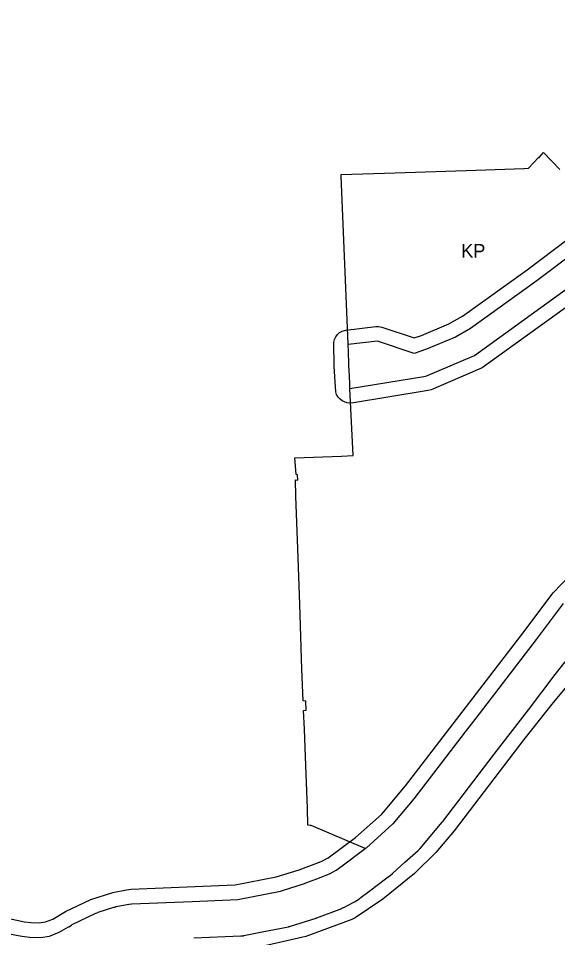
# Model space of a CAD drawing. Extents: x 7428080 to 7432143, y 5545880 to 5549217.
# Drawn here: x 7429439.3 to 7429660.4, y 5546644.6 to 5547021.6 of the extents above; entities that cross this region are included whole.
import ezdxf

# ---------------------------------------------------------------- set-up
doc = ezdxf.new("R2010")
doc.units = 0
for name, color, linetype in [('CZ_L_linie rozgraniczające tereny o różnym przeznaczeniu oraz różnych warunkach ich zabudowy i zagospodarowania', 7, 'Continuous'), ('CZ_L_maksymalne nieprzekraczalne linie zabudowy', 7, 'Continuous'), ('CZ_L_opisy_linie rozgraniczające tereny o różnym przeznaczeniu oraz różnych warunkach ich zabudowy i zagospodarowania', 7, 'Continuous')]:
    doc.layers.add(name, color=color, linetype=linetype)

msp = doc.modelspace()

# ---------------------------------------------------------------- linework, layer by layer
at = {"layer": 'CZ_L_linie rozgraniczające tereny o różnym przeznaczeniu oraz różnych warunkach ich zabudowy i zagospodarowania'}
for p, q in [((7429652.76, 5546964.51), (7429653.66, 5546965.56)), ((7429653.66, 5546965.56), (7429654.57, 5546966.64)), ((7429654.57, 5546966.64), (7429661.31, 5546959.61)), ((7429648.41, 5546960.26), (7429652.59, 5546964.55)), ((7429652.59, 5546964.55), (7429652.62, 5546964.67)), ((7429652.62, 5546964.67), (7429652.66, 5546964.62)), ((7429652.66, 5546964.62), (7429652.76, 5546964.51)), ((7429571.61, 5546957.53), (7429593.78, 5546958.24)), ((7429593.78, 5546958.24), (7429627.02, 5546959.43)), ((7429627.02, 5546959.43), (7429646.55, 5546960.01)), ((7429646.55, 5546960.01), (7429646.7, 5546960.03)), ((7429646.7, 5546960.03), (7429648.41, 5546960.26)), ((7429571.55, 5546956.84), (7429571.61, 5546957.53)), ((7429574.52, 5546888.1), (7429571.55, 5546956.84)), ((7429684.54, 5546938.62), (7429651.42, 5546913.65)), ((7429651.42, 5546913.65), (7429624.59, 5546894.44)), ((7429624.59, 5546894.44), (7429618.47, 5546890.9)), ((7429618.47, 5546890.9), (7429606.67, 5546885.9)), ((7429574.53, 5546887.87), (7429574.52, 5546888.1)), ((7429586.45, 5546889.23), (7429574.53, 5546887.87)), ((7429574.6, 5546884.87), (7429574.53, 5546887.87)), ((7429601.5, 5546884.24), (7429586.45, 5546889.23)), ((7429574.72, 5546879.87), (7429574.6, 5546884.87)), ((7429606.67, 5546885.9), (7429601.5, 5546884.24)), ((7429574.74, 5546879.06), (7429574.72, 5546879.87)), ((7429574.97, 5546874.96), (7429574.74, 5546879.06)), ((7429575.14, 5546871.42), (7429574.97, 5546874.96)), ((7429575.21, 5546869.82), (7429575.14, 5546871.42)), ((7429576.52, 5546842.27), (7429575.21, 5546869.82)), ((7429552.56, 5546841.32), (7429571.74, 5546842.1)), ((7429553.1, 5546834.5), (7429552.56, 5546841.32)), ((7429571.74, 5546842.1), (7429576.52, 5546842.27)), ((7429553.72, 5546834.43), (7429553.1, 5546834.5)), ((7429553.81, 5546832.24), (7429553.72, 5546834.43)), ((7429552.98, 5546825.67), (7429552.84, 5546832.29)), ((7429552.84, 5546832.29), (7429553.81, 5546832.24)), ((7429553.81, 5546804.08), (7429552.98, 5546825.67)), ((7429554.69, 5546781.35), (7429553.81, 5546804.08)), ((7429555.55, 5546754.68), (7429554.69, 5546781.35)), ((7429662.65, 5546781.62), (7429651.62, 5546766.91)), ((7429651.62, 5546766.91), (7429626.79, 5546734.57)), ((7429556.08, 5546741.71), (7429555.55, 5546754.68)), ((7429659.42, 5546752.44), (7429663.45, 5546757.68)), ((7429648.37, 5546738.05), (7429659.42, 5546752.44)), ((7429557.13, 5546741.58), (7429556.08, 5546741.71)), ((7429557.28, 5546737.9), (7429557.13, 5546741.58)), ((7429556.24, 5546737.69), (7429557.28, 5546737.9)), ((7429556.58, 5546730.1), (7429556.24, 5546737.69)), ((7429634.38, 5546719.82), (7429648.37, 5546738.05)), ((7429626.79, 5546734.57), (7429622.47, 5546728.95)), ((7429556.56, 5546730.09), (7429556.58, 5546730.1)), ((7429556.98, 5546718.71), (7429556.56, 5546730.09)), ((7429622.47, 5546728.94), (7429601.45, 5546701.48)), ((7429622.47, 5546728.95), (7429622.47, 5546728.94)), ((7429557.76, 5546697.63), (7429556.98, 5546718.71)), ((7429613.26, 5546692.23), (7429634.38, 5546719.82)), ((7429601.45, 5546701.48), (7429592.81, 5546691.19)), ((7429558.01, 5546690.75), (7429557.76, 5546697.63)), ((7429558.95, 5546690.57), (7429558.01, 5546690.75)), ((7429559.3, 5546690.51), (7429558.95, 5546690.57)), ((7429581.51, 5546681.09), (7429559.3, 5546690.51)), ((7429592.81, 5546691.19), (7429581.81, 5546681.33)), ((7429603.95, 5546681.14), (7429613.04, 5546691.96)), ((7429613.04, 5546691.96), (7429613.06, 5546691.99)), ((7429613.06, 5546691.99), (7429613.21, 5546692.17)), ((7429613.21, 5546692.17), (7429613.22, 5546692.18)), ((7429613.22, 5546692.18), (7429613.26, 5546692.23)), ((7429571.99, 5546674.03), (7429581.51, 5546681.09)), ((7429581.71, 5546681.24), (7429581.51, 5546681.09)), ((7429581.81, 5546681.33), (7429581.71, 5546681.24)), ((7429598.81, 5546676.43), (7429603.22, 5546680.37)), ((7429603.22, 5546680.37), (7429603.26, 5546680.42)), ((7429603.26, 5546680.42), (7429603.27, 5546680.42)), ((7429603.27, 5546680.42), (7429603.67, 5546680.82)), ((7429603.67, 5546680.82), (7429603.69, 5546680.85)), ((7429603.69, 5546680.85), (7429603.72, 5546680.87)), ((7429603.72, 5546680.87), (7429603.82, 5546681.01)), ((7429603.82, 5546681.01), (7429603.91, 5546681.08)), ((7429603.91, 5546681.08), (7429603.93, 5546681.12)), ((7429603.93, 5546681.12), (7429603.95, 5546681.14)), ((7429592.74, 5546670.98), (7429597.76, 5546675.48)), ((7429597.76, 5546675.48), (7429598.81, 5546676.43)), ((7429567.06, 5546670.94), (7429569.61, 5546672.27)), ((7429569.61, 5546672.27), (7429571.99, 5546674.03)), ((7429557.17, 5546667.06), (7429561.62, 5546668.75)), ((7429561.62, 5546668.75), (7429566.12, 5546670.45)), ((7429566.12, 5546670.45), (7429567.06, 5546670.94)), ((7429585.3, 5546665.29), (7429591.5, 5546669.88)), ((7429591.5, 5546669.88), (7429591.58, 5546669.95)), ((7429591.58, 5546669.95), (7429591.62, 5546669.98)), ((7429591.62, 5546669.98), (7429592.66, 5546670.93)), ((7429592.66, 5546670.93), (7429592.74, 5546670.98)), ((7429529.29, 5546660.22), (7429546.69, 5546663.68)), ((7429546.69, 5546663.68), (7429547.54, 5546663.95)), ((7429547.54, 5546663.95), (7429556.55, 5546666.83)), ((7429556.55, 5546666.83), (7429557.17, 5546667.06)), ((7429579.78, 5546661.14), (7429585.06, 5546665.05)), ((7429585.06, 5546665.05), (7429585.27, 5546665.24)), ((7429585.27, 5546665.24), (7429585.3, 5546665.29)), ((7429510.58, 5546659.46), (7429529.29, 5546660.22)), ((7429578.07, 5546659.87), (7429578.44, 5546660.14)), ((7429578.44, 5546660.14), (7429579.78, 5546661.14)), ((7429471.93, 5546654.96), (7429478.47, 5546657.08)), ((7429478.47, 5546657.08), (7429478.56, 5546657.1)), ((7429478.56, 5546657.1), (7429478.67, 5546657.13)), ((7429478.67, 5546657.13), (7429478.89, 5546657.17)), ((7429478.89, 5546657.17), (7429479.19, 5546657.27)), ((7429479.19, 5546657.27), (7429479.27, 5546657.28)), ((7429479.27, 5546657.28), (7429479.37, 5546657.31)), ((7429479.37, 5546657.31), (7429484.62, 5546658.32)), ((7429484.62, 5546658.32), (7429484.71, 5546658.33)), ((7429484.71, 5546658.33), (7429484.73, 5546658.34)), ((7429484.73, 5546658.34), (7429485.62, 5546658.44)), ((7429485.62, 5546658.44), (7429485.67, 5546658.43)), ((7429485.67, 5546658.43), (7429485.73, 5546658.45)), ((7429485.73, 5546658.45), (7429510.58, 5546659.46)), ((7429561.68, 5546652.73), (7429571.85, 5546656.59)), ((7429571.85, 5546656.59), (7429571.89, 5546656.61)), ((7429571.89, 5546656.61), (7429571.95, 5546656.63)), ((7429571.95, 5546656.63), (7429572.16, 5546656.75)), ((7429572.16, 5546656.75), (7429572.24, 5546656.8)), ((7429572.24, 5546656.8), (7429572.35, 5546656.83)), ((7429572.35, 5546656.83), (7429572.6, 5546656.92)), ((7429572.6, 5546656.92), (7429572.63, 5546656.94)), ((7429572.63, 5546656.94), (7429572.66, 5546656.95)), ((7429572.66, 5546656.95), (7429574.24, 5546657.77)), ((7429574.24, 5546657.77), (7429577.07, 5546659.24)), ((7429577.07, 5546659.24), (7429577.11, 5546659.28)), ((7429577.11, 5546659.28), (7429577.29, 5546659.38)), ((7429577.29, 5546659.38), (7429577.37, 5546659.44)), ((7429577.37, 5546659.44), (7429577.94, 5546659.78)), ((7429577.94, 5546659.78), (7429577.98, 5546659.82)), ((7429577.98, 5546659.82), (7429578.07, 5546659.87)), ((7429461.39, 5546649.96), (7429470.99, 5546654.59)), ((7429470.99, 5546654.59), (7429471.01, 5546654.59)), ((7429471.01, 5546654.59), (7429471.02, 5546654.6)), ((7429471.02, 5546654.6), (7429471.06, 5546654.61)), ((7429471.06, 5546654.61), (7429471.1, 5546654.64)), ((7429471.1, 5546654.64), (7429471.15, 5546654.65)), ((7429471.15, 5546654.65), (7429471.18, 5546654.67)), ((7429471.18, 5546654.67), (7429471.85, 5546654.93)), ((7429471.85, 5546654.93), (7429471.87, 5546654.94)), ((7429471.87, 5546654.94), (7429471.93, 5546654.96)), ((7429550.85, 5546649.26), (7429561.31, 5546652.6)), ((7429561.31, 5546652.6), (7429561.38, 5546652.63)), ((7429561.38, 5546652.63), (7429561.39, 5546652.63)), ((7429561.39, 5546652.63), (7429561.62, 5546652.72)), ((7429561.62, 5546652.72), (7429561.68, 5546652.73)), ((7429456.06, 5546646.84), (7429459.86, 5546648.97)), ((7429459.86, 5546648.97), (7429459.88, 5546648.98)), ((7429459.88, 5546648.98), (7429459.96, 5546649.05)), ((7429459.96, 5546649.05), (7429461.05, 5546649.75)), ((7429461.05, 5546649.75), (7429461.14, 5546649.81)), ((7429461.14, 5546649.81), (7429461.37, 5546649.95)), ((7429461.37, 5546649.95), (7429461.39, 5546649.96)), ((7429539.25, 5546646.9), (7429550.03, 5546649.05)), ((7429550.03, 5546649.05), (7429550.13, 5546649.08)), ((7429550.13, 5546649.08), (7429550.21, 5546649.1)), ((7429550.21, 5546649.1), (7429550.46, 5546649.18)), ((7429550.46, 5546649.18), (7429550.65, 5546649.21)), ((7429550.65, 5546649.21), (7429550.75, 5546649.25)), ((7429550.75, 5546649.25), (7429550.85, 5546649.26)), ((7429435.69, 5546646.19), (7429440.64, 5546645.18)), ((7429440.64, 5546645.18), (7429443.99, 5546644.76)), ((7429448.28, 5546644.69), (7429452, 5546645.16)), ((7429452, 5546645.16), (7429456.06, 5546646.84)), ((7429511.19, 5546644.47), (7429530.49, 5546645.25)), ((7429530.49, 5546645.25), (7429530.55, 5546645.27)), ((7429530.55, 5546645.27), (7429530.6, 5546645.26)), ((7429530.6, 5546645.26), (7429531.53, 5546645.37)), ((7429531.53, 5546645.37), (7429531.56, 5546645.38)), ((7429531.56, 5546645.38), (7429531.65, 5546645.39)), ((7429531.65, 5546645.39), (7429539.25, 5546646.9)), ((7429443.99, 5546644.76), (7429448.28, 5546644.69))]:
    msp.add_line(p, q, dxfattribs=at)
msp.add_lwpolyline([(7429575.21, 5546869.82), (7429606.33, 5546874.9), (7429626.24, 5546883.33), (7429672.75, 5546916.96), (7429704.62, 5546940.48), (7429717.09, 5546949.4), (7429717.11, 5546949.41), (7429717.14, 5546949.43), (7429738.96, 5546965.38), (7429758.47, 5546979.11), (7429785.6, 5546997.84), (7429804.56, 5547008.96), (7429820.45, 5547015.66), (7429847.88, 5547021.13), (7429872.96, 5547021.63), (7429894.1, 5547020.91), (7429898.8, 5547014.91)], dxfattribs=at)
at = {"layer": 'CZ_L_maksymalne nieprzekraczalne linie zabudowy'}
for points in [[(7429676.28, 5546912.11), (7429629.45, 5546878.26), (7429608.49, 5546869.3), (7429607.3, 5546868.98), (7429575.85, 5546863.86), (7429573.89, 5546863.97), (7429572.08, 5546864.7), (7429571.14, 5546865.41), (7429570.36, 5546866.29), (7429569.77, 5546867.3), (7429569.38, 5546868.41), (7429568.74, 5546878.81), (7429568.6, 5546888.8), (7429568.89, 5546889.94), (7429569.41, 5546891), (7429570.11, 5546891.94), (7429570.99, 5546892.72), (7429572.01, 5546893.32), (7429573.5, 5546893.78), (7429585.81, 5546895.2), (7429586.99, 5546895.21), (7429588.33, 5546894.93), (7429601.53, 5546890.55), (7429604.58, 5546891.53), (7429615.79, 5546896.28), (7429621.34, 5546899.49), (7429647.87, 5546918.48), (7429681.01, 5546943.47)], [(7429435.55, 5546652.43), (7429441.84, 5546651.07), (7429444.34, 5546650.76), (7429447.85, 5546650.7), (7429450.37, 5546651), (7429453.33, 5546652.2), (7429458.55, 5546655.25), (7429468.93, 5546660.23), (7429478, 5546663.15), (7429483.62, 5546664.24), (7429485.49, 5546664.44), (7429528.18, 5546666.18), (7429544.96, 5546669.45), (7429554.41, 5546672.44), (7429563.45, 5546675.86), (7429566.34, 5546677.33), (7429577.54, 5546685.61), (7429588.09, 5546695.02), (7429589, 5546695.99), (7429597.98, 5546706.81), (7429645.22, 5546768.42), (7429658.48, 5546785.99), (7429665.62, 5546793.33)], [(7429666.25, 5546750.2), (7429658.48, 5546741.07), (7429646.57, 5546725.83), (7429617.92, 5546688.45), (7429610.42, 5546679.51), (7429601.67, 5546670.93), (7429588.7, 5546660.29), (7429577.39, 5546652.67), (7429576.02, 5546652.03), (7429557.18, 5546644.99), (7429532.57, 5546639.47)]]:
    msp.add_lwpolyline(points, dxfattribs=at)

# ---------------------------------------------------------------- texts
at = {"layer": 'CZ_L_opisy_linie rozgraniczające tereny o różnym przeznaczeniu oraz różnych warunkach ich zabudowy i zagospodarowania'}
msp.add_text('KP', height=5.549, dxfattribs=at).set_placement((7429620.83, 5546923.54))

doc.saveas('drawing.dxf')
